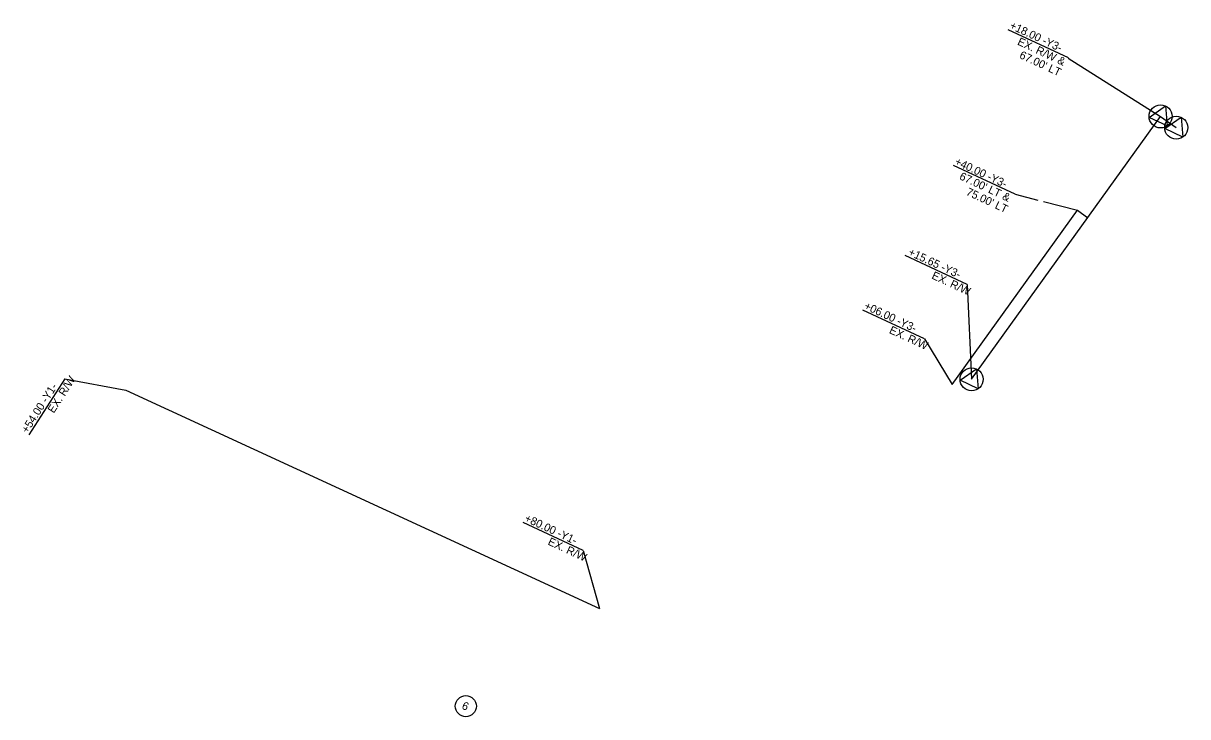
# Model space of a CAD drawing. Extents: x 2345854 to 2349056, y 842589 to 845145.
# Drawn here: x 2348328 to 2349056, y 843698 to 844131 of the extents above; entities that cross this region are included whole.
import ezdxf

# ---------------------------------------------------------------- set-up
doc = ezdxf.new("R2010")
doc.units = 0
for name, color, linetype in [('Prop Easement Construction', 7, 'Continuous'), ('Prop Easement Construction Station Offsets', 7, 'Continuous'), ('Prop Parcel Number Text', 7, 'Continuous'), ('Prop ROW Marker CELL', 7, 'Continuous'), ('Prop ROW RW CA Lines', 7, 'Continuous'), ('Prop ROW Station Offsets', 7, 'Continuous')]:
    doc.layers.add(name, color=color, linetype=linetype)

msp = doc.modelspace()

# ---------------------------------------------------------------- linework, layer by layer
at = {"layer": 'Prop Easement Construction'}
for p, q in [((2348908.78, 843905.57), (2348987.02, 844014.35)), ((2348987.02, 844014.35), (2348993.52, 844009.68)), ((2348392.33, 843901.88), (2348688.48, 843765.58))]:
    msp.add_line(p, q, dxfattribs=at)
at = {"layer": 'Prop Easement Construction Station Offsets'}
for p, q in [((2348948.25, 844024.43), (2348909.56, 844042.44)), ((2348891.57, 843933.94), (2348852.88, 843951.95)), ((2348354.19, 843909), (2348331.8, 843874.08)), ((2348678.27, 843801.75), (2348640.67, 843819.26))]:
    msp.add_line(p, q, dxfattribs=at)
for points in [[(2348948.25, 844024.43), (2348962.36, 844020.76)], [(2348965.78, 844019.87), (2348987.02, 844014.35)], [(2348891.57, 843933.94), (2348908.78, 843905.57)], [(2348354.19, 843909), (2348392.33, 843901.88)], [(2348678.27, 843801.75), (2348688.48, 843765.58)]]:
    msp.add_lwpolyline(points, dxfattribs=at)
at = {"layer": 'Prop Parcel Number Text'}
msp.add_circle((2348604.88, 843704.43), 6.58, dxfattribs=at)
at = {"layer": 'Prop ROW Marker CELL'}
for p, q in [((2349039.06, 844073.01), (2349039.06, 844073.01)), ((2349048.8, 844066), (2349048.8, 844066)), ((2348920.92, 843908.73), (2348920.92, 843908.73))]:
    msp.add_line(p, q, dxfattribs=at)
for points in [[(2349031.87, 844072.38), (2349042.09, 844079.54), (2349043.2, 844067.11)], [(2349041.61, 844065.38), (2349051.84, 844072.53), (2349052.94, 844060.1)], [(2348913.73, 843908.1), (2348923.96, 843915.25), (2348925.06, 843902.82)]]:
    msp.add_lwpolyline(points, close=True, dxfattribs=at)
for centre in [(2349039.06, 844073.01), (2349048.8, 844066), (2348920.92, 843908.73)]:
    msp.add_circle(centre, 7.2, dxfattribs=at)
at = {"layer": 'Prop ROW RW CA Lines'}
for p, q in [((2348920.92, 843908.73), (2349039.06, 844073.01)), ((2349039.06, 844073.01), (2349048.8, 844066))]:
    msp.add_line(p, q, dxfattribs=at)
at = {"layer": 'Prop ROW Station Offsets'}
for p, q in [((2348981.44, 844109.7), (2348943.83, 844127.2)), ((2348918.1, 843968.05), (2348879.42, 843986.06))]:
    msp.add_line(p, q, dxfattribs=at)
for points in [[(2348981.35, 844109.51), (2349039.06, 844073.01)], [(2348918.1, 843968.05), (2348920.92, 843908.73)]]:
    msp.add_lwpolyline(points, dxfattribs=at)

# ---------------------------------------------------------------- texts
at = {"layer": 'Prop Easement Construction Station Offsets'}
for s, rotation, p in [('+40.00 -Y3-', 335.03685, (2348909.88, 844043.13)), ("67.00' LT &", 335.03685, (2348912.88, 844033.92)), ("75.00' LT", 335.03685, (2348917.06, 844024.16)), ('+06.00 -Y3-', 335.03685, (2348853.32, 843952.9)), ('EX. R/W', 335.03685, (2348869, 843937.79)), ('EX. R/W', 57.32812, (2348347.36, 843887.15)), ('+54.00 -Y1-', 57.32812, (2348330.92, 843874.65)), ('+80.00 -Y1-', 335.03685, (2348641.11, 843820.2)), ('EX. R/W', 335.03685, (2348655.7, 843805.6))]:
    msp.add_text(s, height=5, rotation=rotation, dxfattribs=at).set_placement(p)
at = {"layer": 'Prop Parcel Number Text'}
msp.add_text('6', height=5, rotation=335.03685, dxfattribs=at).set_placement((2348601.89, 843703.07))
at = {"layer": 'Prop ROW Station Offsets'}
for s, p in [('+18.00 -Y3-', (2348944.27, 844128.15)), ('EX. R/W &', (2348949.15, 844118.06)), ("67.00' LT", (2348950.37, 844109.68)), ('+15.65 -Y3-', (2348880.94, 843986.5)), ('EX. R/W', (2348895.54, 843971.89))]:
    msp.add_text(s, height=5, rotation=335.03685, dxfattribs=at).set_placement(p)

doc.saveas('drawing.dxf')
